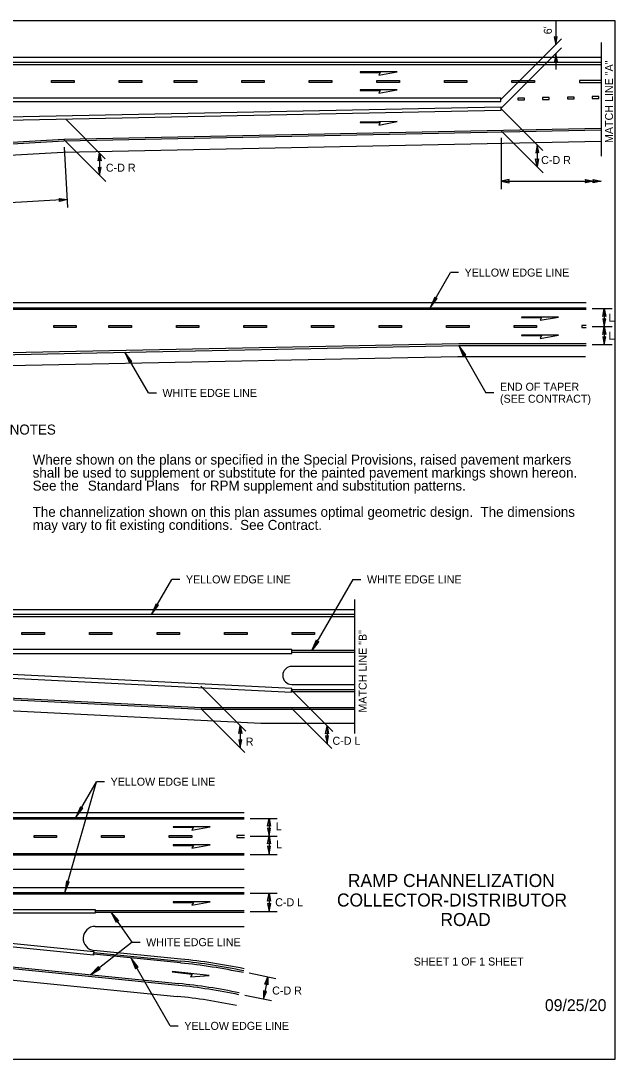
# Model space of a CAD drawing. Extents: x 99862 to 103151, y 100000 to 102076.
# Drawn here: x 101963 to 103151, y 100000 to 102076 of the extents above; entities that cross this region are included whole.
import ezdxf

# ---------------------------------------------------------------- set-up
doc = ezdxf.new("R2010")
doc.units = 0
for name, color, linetype in [('Level 1', 7, 'Continuous'), ('Level 15', 7, 'Continuous'), ('Level 2', 7, 'Continuous'), ('Level 20', 7, 'Continuous'), ('Level 3', 7, 'Continuous'), ('Level 4', 7, 'Continuous'), ('Level 5', 7, 'Continuous'), ('Level 6', 7, 'Continuous'), ('Level 60', 7, 'Continuous'), ('Level 62', 7, 'Continuous'), ('Level 7', 7, 'Continuous')]:
    doc.layers.add(name, color=color, linetype=linetype)

msp = doc.modelspace()

# ---------------------------------------------------------------- linework, layer by layer
at = {"layer": 'Level 1'}
msp.add_lwpolyline([(99862, 99999.5), (103151, 99999.5), (103151, 102075.5), (99862, 102075.5)], close=True, dxfattribs=at)
at = {"layer": 'Level 15'}
for p, q in [((103032.3, 102075.1), (103032.3, 102027.7)), ((103043.7, 102039.1), (102922.6, 101918)), ((103043.6, 102021.1), (102922.4, 101900)), ((103032.3, 102009.8), (103032.3, 101977.8)), ((102922.4, 101900), (103006.2, 101816.2)), ((102053, 101878.6), (102131.9, 101799.8)), ((102053, 101878.6), (102131.9, 101799.8)), ((102923.5, 101855.1), (103007.1, 101771.5)), ((102048.5, 101838.5), (102132.7, 101754.2)), ((102923.3, 101841.4), (102923.3, 101738.9)), ((102049.7, 101823.1), (102056.7, 101702.3)), ((102120.5, 101811.1), (102120.5, 101775.4)), ((102120.5, 101811.1), (102120.5, 101766.6)), ((102120.5, 101811.1), (102120.5, 101775.4)), ((102994.9, 101827.6), (102994.9, 101783.7)), ((102923.3, 101754.9), (103122.6, 101754.9)), ((102781.5, 101501.9), (102822, 101572.1)), ((102781.5, 101501.9), (102822, 101572.1)), ((102838, 101572.1), (102822, 101572.1)), ((102838, 101572.1), (102822, 101572.1)), ((103105.1, 101500), (103145, 101500)), ((103129, 101500), (103129, 101464.3)), ((103105.1, 101464.2), (103145, 101464.2)), ((103129, 101464.2), (103129, 101428.5)), ((102218.2, 101331.5), (102171.3, 101412.8)), ((102218.2, 101331.5), (102171.3, 101412.8)), ((102838.2, 101426.2), (102892.7, 101331.9)), ((102838.2, 101426.2), (102892.7, 101331.9)), ((103105.1, 101428.1), (103145, 101428.1)), ((102218.2, 101331.5), (102234.2, 101331.5)), ((102218.2, 101331.5), (102234.2, 101331.5)), ((102908.7, 101331.9), (102892.7, 101331.9)), ((102908.7, 101331.9), (102892.7, 101331.9)), ((102224.6, 100888.6), (102265.1, 100958.7)), ((102281.1, 100958.7), (102265.1, 100958.7)), ((102281.1, 100958.7), (102265.1, 100958.7)), ((102626.9, 100958.7), (102544.8, 100816.6)), ((102626.9, 100958.7), (102642.9, 100958.7)), ((102626.9, 100958.7), (102642.9, 100958.7)), ((102322.9, 100745.3), (102412.9, 100655.3)), ((102504.6, 100736.6), (102586.5, 100654.7)), ((102322.9, 100700.8), (102410.8, 100612.9)), ((102504.6, 100700.7), (102584.8, 100620.5)), ((102401.6, 100666.6), (102401.6, 100630.9)), ((102575.2, 100666), (102575.2, 100630.3)), ((102575.2, 100666), (102575.2, 100630.3)), ((102050.8, 100332.9), (102114.5, 100554.3)), ((102073.3, 100482.9), (102114.5, 100554.3)), ((102130.5, 100554.3), (102114.5, 100554.3)), ((102130.5, 100554.3), (102114.5, 100554.3)), ((102421.4, 100481), (102475.4, 100481)), ((102421.4, 100481), (102475.4, 100481)), ((102459.3, 100481.5), (102459.3, 100445.8)), ((102459.3, 100481.5), (102459.3, 100445.8)), ((102421.4, 100445.2), (102475.4, 100445.2)), ((102421.4, 100445.2), (102475.4, 100445.2)), ((102459.3, 100445.6), (102459.3, 100410)), ((102459.3, 100445.6), (102459.3, 100410)), ((102421.4, 100409.1), (102475.4, 100409.1)), ((102421.4, 100409.1), (102475.4, 100409.1)), ((102421.4, 100331.2), (102475.4, 100331.2)), ((102459.4, 100331.2), (102459.4, 100295.5)), ((102185.5, 100233.5), (102143.6, 100293.2)), ((102421.4, 100295), (102475.4, 100295)), ((102185.5, 100233.5), (102102.1, 100168.5)), ((102185.5, 100233.5), (102201.5, 100233.5)), ((102261.9, 100066.2), (102183.6, 100201.8)), ((102419.7, 100172), (102473, 100161)), ((102419.7, 100172), (102473, 100161)), ((102456.9, 100164.3), (102448, 100120.7)), ((102410.7, 100127.9), (102464, 100117)), ((102410.7, 100127.9), (102464, 100117)), ((102261.9, 100066.2), (102277.9, 100066.2))]:
    msp.add_line(p, q, dxfattribs=at)
for points in [[(103032.3, 102027.7), (103035, 102043.5), (103032, 102042.7), (103028.9, 102043.3)], [(103032.3, 102009.8), (103029.5, 101994), (103032.6, 101994.8), (103035.7, 101994.2)], [(102120.5, 101811.1), (102123.6, 101795.4), (102120.5, 101796.1), (102117.4, 101795.4)], [(102994.9, 101827.6), (102992.1, 101811.8), (102995.2, 101812.6), (102998.3, 101811.9)], [(102994.9, 101783.7), (102991.5, 101799.3), (102994.6, 101798.7), (102997.6, 101799.5)], [(102120.5, 101766.6), (102123.6, 101782.3), (102120.5, 101781.6), (102117.4, 101782.3)], [(102923.3, 101754.9), (102939.1, 101751.8), (102938.3, 101754.9), (102939.1, 101758)], [(102923.3, 101754.9), (102939.1, 101751.8), (102938.3, 101754.9), (102939.1, 101758)], [(103107.6, 101754.9), (103091.9, 101751.8), (103092.6, 101754.9), (103091.9, 101758)], [(103122.6, 101754.9), (103106.9, 101751.8), (103107.6, 101754.9), (103106.9, 101758)], [(102055.8, 101718.2), (102040.3, 101714.2), (102040.8, 101717.4), (102039.9, 101720.4)], [(102781.5, 101501.9), (102795.5, 101520.2), (102792.4, 101520.8), (102790.3, 101523.2)], [(102781.5, 101501.9), (102795.5, 101520.2), (102792.4, 101520.8), (102790.3, 101523.2)], [(103129, 101500), (103132.1, 101484.3), (103129, 101485), (103126, 101484.3)], [(103129, 101464.2), (103132.1, 101479.9), (103129, 101479.2), (103126, 101479.9)], [(103129, 101464.2), (103132.1, 101448.5), (103129, 101449.2), (103126, 101448.5)], [(103129.1, 101428.1), (103132.2, 101443.8), (103129.1, 101443), (103126, 101443.8)], [(103129.1, 101428.1), (103132.2, 101443.8), (103129.1, 101443), (103126, 101443.8)], [(102171.3, 101412.8), (102180.1, 101391.6), (102182.2, 101394), (102185.3, 101394.6)], [(102171.3, 101412.8), (102180.1, 101391.6), (102182.2, 101394), (102185.3, 101394.6)], [(102838.2, 101426.2), (102847.1, 101404.8), (102849.2, 101407.2), (102852.3, 101407.8)], [(102838.2, 101426.2), (102847.1, 101404.8), (102849.2, 101407.2), (102852.3, 101407.8)], [(102224.6, 100888.6), (102238.6, 100906.9), (102235.5, 100907.4), (102233.5, 100909.8)], [(102224.6, 100888.6), (102238.6, 100906.9), (102235.5, 100907.4), (102233.5, 100909.8)], [(102544.8, 100816.6), (102553.7, 100837.8), (102555.7, 100835.4), (102558.8, 100834.8)], [(102544.8, 100816.6), (102553.7, 100837.8), (102555.7, 100835.4), (102558.8, 100834.8)], [(102401.6, 100666.6), (102404.7, 100650.9), (102401.6, 100651.6), (102398.5, 100650.9)], [(102575.2, 100666), (102578.3, 100650.3), (102575.2, 100651), (102572.1, 100650.3)], [(102575.2, 100666), (102578.3, 100650.3), (102575.2, 100651), (102572.1, 100650.3)], [(102575.2, 100630.2), (102578.3, 100645.9), (102575.2, 100645.2), (102572.1, 100645.9)], [(102575.2, 100630.2), (102578.3, 100645.9), (102575.2, 100645.2), (102572.1, 100645.9)], [(102575.2, 100630.2), (102578.3, 100645.9), (102575.2, 100645.2), (102572.1, 100645.9)], [(102401.6, 100622.1), (102404.7, 100637.8), (102401.6, 100637.1), (102398.5, 100637.8)], [(102073.3, 100482.9), (102087.3, 100501.2), (102084.1, 100501.8), (102082.1, 100504.2)], [(102073.3, 100482.9), (102087.3, 100501.2), (102084.1, 100501.8), (102082.1, 100504.2)], [(102459.3, 100481.5), (102462.3, 100465.7), (102459.3, 100466.5), (102456.2, 100465.7)], [(102459.3, 100481.5), (102462.3, 100465.7), (102459.3, 100466.5), (102456.2, 100465.7)], [(102459.3, 100445.6), (102462.3, 100461.4), (102459.3, 100460.6), (102456.2, 100461.4)], [(102459.3, 100445.6), (102462.3, 100461.4), (102459.3, 100460.6), (102456.2, 100461.4)], [(102459.3, 100445.6), (102462.3, 100429.9), (102459.3, 100430.6), (102456.2, 100429.9)], [(102459.3, 100445.6), (102462.3, 100429.9), (102459.3, 100430.6), (102456.2, 100429.9)], [(102459.4, 100409.5), (102462.4, 100425.2), (102459.4, 100424.5), (102456.3, 100425.2)], [(102459.4, 100409.5), (102462.4, 100425.2), (102459.4, 100424.5), (102456.3, 100425.2)], [(102050.8, 100332.9), (102060, 100354), (102056.8, 100353.8), (102054.3, 100355.7)], [(102459.4, 100331.2), (102462.4, 100315.5), (102459.4, 100316.2), (102456.3, 100315.5)], [(102143.6, 100293.2), (102159.1, 100276.2), (102156.1, 100275.3), (102154.3, 100272.8)], [(102459.4, 100295), (102462.5, 100310.8), (102459.4, 100310), (102456.4, 100310.8)], [(102183.6, 100201.8), (102192.4, 100180.5), (102194.5, 100182.9), (102197.6, 100183.5)], [(102183.6, 100201.8), (102192.4, 100180.5), (102194.5, 100182.9), (102197.6, 100183.5)], [(102102.1, 100168.5), (102122, 100180.2), (102119.3, 100181.9), (102118.3, 100184.9)], [(102456.9, 100164.3), (102456.8, 100148.3), (102453.9, 100149.7), (102450.8, 100149.6)], [(102448, 100120.3), (102454.2, 100135), (102451, 100135), (102448.1, 100136.3)]]:
    msp.add_lwpolyline(points, close=True, dxfattribs=at)
msp.add_lwpolyline([(102055.8, 101718.2), (100875.8, 101649.7)], dxfattribs=at)
at = {"layer": 'Level 2'}
for p, q in [((103122.6, 102002), (99944, 102002)), ((102047.6, 101812.9), (103122.6, 101834.9)), ((100476.9, 101721.6), (102047.6, 101812.9)), ((99911.9, 101512.1), (103093.2, 101512.1)), ((99944, 100898.7), (102630.3, 100898.7)), ((102630.3, 100784.7), (102504.5, 100784.7)), ((102504.5, 100748.7), (102630.3, 100748.7)), ((100224.7, 100493), (102409.4, 100493)), ((102409.4, 100379), (100224.7, 100379)), ((100224.7, 100343), (102409.4, 100343)), ((102111.6, 100265), (102409.4, 100265)), ((102283.2, 100199.7), (102109.2, 100217.1))]:
    msp.add_line(p, q, dxfattribs=at)
for points in [[(103091.7, 101403.9), (102836.7, 101403.9), (99911.9, 101344.9)], [(102630.3, 100670.7), (102442.8, 100670.7), (100162.8, 100784.7), (99944, 100784.7)], [(102630.3, 100670.7), (102442.8, 100670.7), (100162.8, 100784.7), (99944, 100784.7)], [(100224.7, 100265), (100876.6, 100265), (102275.7, 100125.1)]]:
    msp.add_lwpolyline(points, dxfattribs=at)
for centre, radius, start, end in [((102504.5, 100766.7), 18, 90, 270), ((102111.6, 100241), 24, 90, 264.2894), ((102163.2, 98999.7), 1206, 78.2187, 84.2894), ((102163.2, 98999.7), 1131, 78.2051, 84.2894)]:
    msp.add_arc(centre, radius, start, end, dxfattribs=at)
at = {"layer": 'Level 3'}
for p, q in [((103122.6, 101991.9), (99944, 101991.9)), ((103122.6, 101991.9), (99944, 101991.9)), ((99944, 101988.1), (103122.6, 101988.1)), ((100847.9, 101921.7), (102922.5, 101921.7)), ((100847.9, 101921.7), (102922.5, 101921.7)), ((100847.9, 101914.2), (102922.5, 101914.2)), ((100847.9, 101914.2), (102922.5, 101914.2)), ((102922.5, 101914.2), (102922.5, 101921.7)), ((102922.5, 101914.2), (102922.5, 101921.7)), ((99911.9, 101501.9), (103093.2, 101501.9)), ((103093.2, 101498.2), (99911.9, 101498.2)), ((102630.4, 100888.6), (99944, 100888.6)), ((99944, 100884.8), (102630.4, 100884.8)), ((102630.3, 100816.6), (102504.5, 100816.6)), ((102630.3, 100816.6), (102504.5, 100816.6)), ((102630.3, 100812.8), (102504.5, 100812.8)), ((102630.3, 100812.8), (102504.5, 100812.8)), ((102504.5, 100738.6), (102630.3, 100738.6)), ((102504.5, 100738.6), (102630.3, 100738.6)), ((102504.5, 100734.8), (102630.3, 100734.8)), ((102504.5, 100734.8), (102630.3, 100734.8)), ((100224.7, 100482.9), (102409.4, 100482.9)), ((102409.4, 100479.1), (100224.7, 100479.1)), ((100224.7, 100332.9), (102409.4, 100332.9)), ((102409.4, 100329.2), (100224.7, 100329.2))]:
    msp.add_line(p, q, dxfattribs=at)
for points in [[(100847.9, 101854.2), (100847.8, 101861.7), (102922.5, 101903.7), (102922.7, 101896.2)], [(100847.9, 101854.2), (100847.8, 101861.7), (102922.5, 101903.7), (102922.7, 101896.2)], [(102504.5, 100810.9), (102504.5, 100818.4), (100944.5, 100818.4), (100944.3, 100811), (102504.3, 100733), (102504.7, 100740.4), (101102.5, 100810.9)], [(102109, 100214.9), (102108.2, 100207.4), (101269.7, 100291.3), (101270.1, 100298.8), (102111.6, 100298.8), (102111.6, 100291.3), (101345.3, 100291.3)]]:
    msp.add_lwpolyline(points, close=True, dxfattribs=at)
msp.add_lwpolyline([(102282.4, 100191.9), (102108.4, 100209.3), (102108.8, 100213), (102282.8, 100195.6)], dxfattribs=at)
msp.add_lwpolyline([(102282.4, 100191.9), (102108.4, 100209.3), (102108.8, 100213), (102282.8, 100195.6)], dxfattribs=at)
for radius, start in [(1198.1, 78.2174), (1198.1, 78.2174), (1201.9, 78.218)]:
    msp.add_arc((102163.2, 98999.7), radius, start, 84.2894, dxfattribs=at)
at = {"layer": 'Level 4'}
for p, q in [((100224.7, 100410.9), (102409.4, 100410.9)), ((102409.4, 100407.2), (100224.7, 100407.2)), ((102111.6, 100296.9), (102409.4, 100296.9)), ((102111.6, 100296.9), (102409.4, 100296.9)), ((102111.6, 100293.2), (102409.4, 100293.2)), ((102111.6, 100293.2), (102409.4, 100293.2))]:
    msp.add_line(p, q, dxfattribs=at)
for points in [[(102024.7, 101956.1), (102069.7, 101956.1), (102069.7, 101952.1), (102024.7, 101952.2)], [(102159.7, 101956.1), (102204.7, 101956.1), (102204.7, 101952.1), (102159.7, 101952.2)], [(102269.7, 101956.1), (102314.7, 101956.1), (102314.7, 101952.1), (102269.7, 101952.2)], [(102404.7, 101956.1), (102449.7, 101956.1), (102449.7, 101952.1), (102404.7, 101952.2)], [(102539.7, 101956.1), (102584.7, 101956.1), (102584.7, 101952.1), (102539.7, 101952.2)], [(102674.7, 101956.1), (102719.7, 101956.1), (102719.7, 101952.1), (102674.7, 101952.2)], [(102809.7, 101956.1), (102854.7, 101956.1), (102854.7, 101952.1), (102809.7, 101952.2)], [(102944.7, 101956.1), (102989.7, 101956.1), (102989.7, 101952.1), (102944.7, 101952.2)], [(102956.3, 101917.2), (102969.8, 101917.2), (102969.8, 101920.9), (102956.3, 101920.9)], [(103005.8, 101918.2), (103019.3, 101918.2), (103019.3, 101922), (103005.8, 101922)], [(103055.3, 101919.3), (103068.8, 101919.3), (103068.8, 101923), (103055.3, 101923)], [(103104.8, 101920.3), (103118.3, 101920.3), (103118.3, 101924.1), (103104.8, 101924.1)], [(102029, 101466.2), (102074, 101466.2), (102074, 101462.2), (102029, 101462.2)], [(102184, 101462.2), (102139, 101462.2), (102139, 101466.2), (102184, 101466.2)], [(102319, 101462.2), (102274, 101462.2), (102274, 101466.2), (102319, 101466.2)], [(102454, 101462.2), (102409, 101462.2), (102409, 101466.2), (102454, 101466.2)], [(102589, 101462.2), (102544, 101462.2), (102544, 101466.2), (102589, 101466.2)], [(102724, 101462.2), (102679, 101462.2), (102679, 101466.2), (102724, 101466.2)], [(102859, 101462.2), (102814, 101462.2), (102814, 101466.2), (102859, 101466.2)], [(102994, 101462.2), (102949, 101462.2), (102949, 101466.2), (102994, 101466.2)], [(101965.3, 100852.7), (102010.3, 100852.7), (102010.3, 100848.7), (101965.3, 100848.7)], [(102100.3, 100852.7), (102145.3, 100852.7), (102145.3, 100848.7), (102100.3, 100848.7)], [(102235.3, 100852.7), (102280.3, 100852.7), (102280.3, 100848.7), (102235.3, 100848.7)], [(102370.3, 100852.7), (102415.3, 100852.7), (102415.3, 100848.7), (102370.3, 100848.7)], [(102505.3, 100852.7), (102550.3, 100852.7), (102550.3, 100848.7), (102505.3, 100848.7)], [(101989.7, 100447), (102034.7, 100447), (102034.7, 100443), (101989.7, 100443)], [(101989.7, 100447), (102034.7, 100447), (102034.7, 100443), (101989.7, 100443)], [(102124.7, 100447), (102169.7, 100447), (102169.7, 100443), (102124.7, 100443)], [(102124.7, 100447), (102169.7, 100447), (102169.7, 100443), (102124.7, 100443)], [(102259.7, 100447), (102304.7, 100447), (102304.7, 100443), (102259.7, 100443)], [(102259.7, 100447), (102304.7, 100447), (102304.7, 100443), (102259.7, 100443)]]:
    msp.add_lwpolyline(points, close=True, dxfattribs=at)
for points in [[(103122.6, 101956.1), (103079.7, 101956.1), (103079.7, 101952.2), (103122.6, 101952.1)], [(100475.1, 101747.4), (102048.8, 101838.9), (103122.6, 101860.8)], [(103122.6, 101857.1), (102049, 101835.1), (100475.5, 101743.7)], [(103093.1, 101466.2), (103084, 101466.2), (103084, 101462.2), (103093.1, 101462.2)], [(103093.1, 101466.2), (103084, 101466.2), (103084, 101462.2), (103093.1, 101462.2)], [(103093.2, 101429.9), (102838.2, 101429.9), (99911.9, 101370.9)], [(99944, 100816.6), (100043.4, 100816.6), (102323.5, 100702.6), (102630.3, 100702.6)], [(102630.3, 100698.8), (102323.3, 100698.8), (100043.4, 100812.8), (99944, 100812.8)], [(102410, 100447), (102394.7, 100447), (102394.7, 100443), (102410, 100443)], [(102410, 100447), (102394.7, 100447), (102394.7, 100443), (102410, 100443)], [(100224.7, 100296.9), (100818, 100296.9), (102278.3, 100150.9)], [(102277.9, 100147.1), (100817.6, 100293.2), (100224.7, 100293.2)]]:
    msp.add_lwpolyline(points, dxfattribs=at)
for centre, radius, start, end in [((102163.2, 98999.7), 1153.1, 78.2093, 84.2894), ((102163.2, 98999.7), 1153.1, 78.2093, 84.2894), ((102162.7, 98997.1), 1159.5, 78.2134, 84.279), ((102162.7, 98997.1), 1159.5, 78.2134, 84.279)]:
    msp.add_arc(centre, radius, start, end, dxfattribs=at)
at = {"layer": 'Level 5'}
for points in [[(102641.4, 101972.1), (102681.4, 101972.1), (102678.3, 101966.6), (102715.2, 101973.2), (102641.4, 101973.2)], [(102641.4, 101972.1), (102681.4, 101972.1), (102678.3, 101966.6), (102715.2, 101973.2), (102641.4, 101973.2)], [(102641.4, 101936), (102681.4, 101936), (102678.3, 101930.5), (102715.2, 101937.1), (102641.4, 101937.1)], [(102641.4, 101936), (102681.4, 101936), (102678.3, 101930.5), (102715.2, 101937.1), (102641.4, 101937.1)], [(102641.4, 101871.8), (102681.4, 101872.3), (102678.4, 101866.8), (102715.2, 101873.9), (102641.4, 101872.8)], [(102641.4, 101871.8), (102681.4, 101872.3), (102678.4, 101866.8), (102715.2, 101873.9), (102641.4, 101872.8)], [(102963.8, 101482.2), (103003.8, 101482.2), (103000.7, 101476.7), (103037.6, 101483.2), (102963.8, 101483.2)], [(102963.8, 101482.2), (103003.8, 101482.2), (103000.7, 101476.7), (103037.6, 101483.2), (102963.8, 101483.2)], [(102963.8, 101446.1), (103003.8, 101446.1), (103000.7, 101440.6), (103037.6, 101447.1), (102963.8, 101447.1)], [(102963.8, 101446.1), (103003.8, 101446.1), (103000.7, 101440.6), (103037.6, 101447.1), (102963.8, 101447.1)], [(102267.8, 100463.1), (102307.9, 100463.1), (102304.8, 100457.6), (102341.7, 100464.1), (102267.8, 100464.1)], [(102267.8, 100427), (102307.9, 100427), (102304.8, 100421.5), (102341.7, 100428), (102267.8, 100428)], [(102267.8, 100313), (102307.9, 100313), (102304.8, 100307.6), (102341.7, 100314.1), (102267.8, 100314.1)], [(102265.9, 100174.1), (102305.7, 100169.6), (102302, 100164.5), (102339.4, 100166.8), (102266, 100175.1)]]:
    msp.add_lwpolyline(points, close=True, dxfattribs=at)
at = {"layer": 'Level 6'}
for p, q in [((103122.6, 102032), (103122.6, 101804.9)), ((102630.3, 100918.7), (102630.3, 100650.7))]:
    msp.add_line(p, q, dxfattribs=at)
at = {"layer": 'Level 60'}
msp.add_line((103151, 102075.5), (103151, 102075.5), dxfattribs=at)
at = {"layer": 'Level 7'}
msp.add_lwpolyline([(99911.9, 101367.2), (102838.2, 101426.2), (103093.2, 101426.2)], dxfattribs=at)

# ---------------------------------------------------------------- texts
at = {"layer": 'Level 15'}
msp.add_text('09/25/20', height=23.62, dxfattribs=at).set_placement((103010.5, 100095.8))
at = {"layer": 'Level 20'}
for s, rotation, p in [("6'", 90, (103024.3, 102048.5)), ('MATCH LINE "A"', 90, (103146.6, 101831.1)), ('YELLOW EDGE LINE', 360, (102850, 101564.1)), ('END OF TAPER', 360, (102920.7, 101335.9)), ('(SEE CONTRACT)', 360, (102920.7, 101311.9)), ('YELLOW EDGE LINE', 360, (102293.1, 100950.7)), ('MATCH LINE "B"', 90, (102654.3, 100692.4))]:
    msp.add_text(s, height=16, rotation=rotation, dxfattribs=at).set_placement(p)
for s, height, p in [('C-D R', 16, (102133.2, 101773.8)), ('C-D R', 16, (102133.2, 101773.8)), ('C-D R', 16, (102133.2, 101773.8)), ('C-D R', 16, (103003, 101789.1)), ('L', 16, (103137.8, 101474.2)), ('L', 16, (103137.8, 101438.3)), ('WHITE EDGE LINE', 16, (102246.2, 101323.5)), ('NOTES', 20, (101940.9, 101248.3)), ('Where shown on the plans or specified in the Special Provisions, raised pavement markers', 20, (101986.8, 101188.3)), ('shall be used to supplement or substitute for the painted pavement markings shown hereon.  ', 20, (101986.8, 101162.2)), ('See the ', 20, (101986.8, 101136.2)), ('Standard Plans', 20, (102097.1, 101136.2)), (' for RPM supplement and substitution patterns.', 20, (102294.9, 101136.2)), ('The channelization shown on this plan assumes optimal geometric design.  The dimensions', 20, (101986.8, 101083.8)), ('may vary to fit existing conditions.  See Contract.', 20, (101986.8, 101057.7)), ('WHITE EDGE LINE', 16, (102654.9, 100950.7)), ('R', 16, (102412.7, 100626.5)), ('C-D L', 16, (102586, 100628.1)), ('YELLOW EDGE LINE', 16, (102142.5, 100546.3)), ('L', 16, (102472.7, 100457.3)), ('L', 16, (102473.4, 100421.4)), ('C-D L', 16, (102471.5, 100305.3)), ('WHITE EDGE LINE', 16, (102213.5, 100225.5)), ('C-D R', 16, (102465.5, 100128.8)), ('YELLOW EDGE LINE', 16, (102289.9, 100058.2))]:
    msp.add_text(s, height=height, dxfattribs=at).set_placement(p)
at = {"layer": 'Level 62'}
for s, height, p in [('RAMP CHANNELIZATION', 26, (102616.8, 100343.8)), ('COLLECTOR-DISTRIBUTOR', 26, (102594.9, 100304.8)), ('ROAD', 26, (102801.7, 100265.8)), ('SHEET 1 OF 1 SHEET', 16, (102748.2, 100186.8))]:
    msp.add_text(s, height=height, dxfattribs=at).set_placement(p)

doc.saveas('drawing.dxf')
